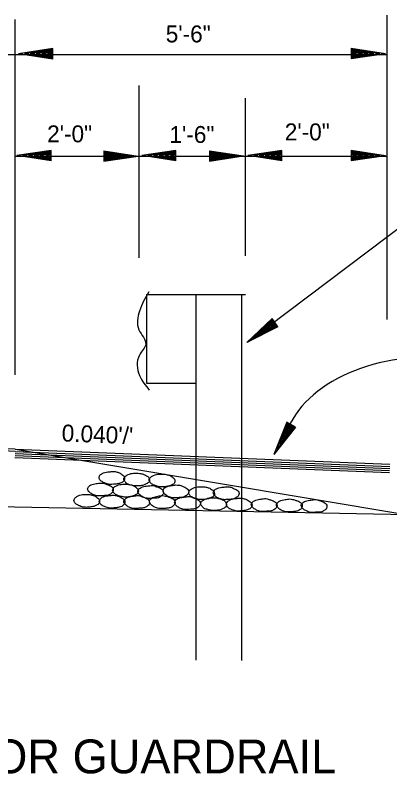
# Model space of a CAD drawing. Extents: x 1955771 to 1955918, y 566326 to 566544.
# Drawn here: x 1955790.88 to 1955804.18, y 566509.34 to 566536.24 of the extents above; entities that cross this region are included whole.
import ezdxf

# ---------------------------------------------------------------- set-up
doc = ezdxf.new("R2010")
doc.units = 0
doc.layers.add('Default', color=7, linetype='Continuous')

msp = doc.modelspace()

# ---------------------------------------------------------------- linework, layer by layer
at = {"layer": 'Default'}
for p, q in [((1955790.882, 566523.482), (1955790.882, 566536.079)), ((1955804.086, 566525.446), (1955804.086, 566536.235)), ((1955792.218, 566535.048), (1955791.001, 566534.866)), ((1955792.218, 566535.017), (1955791.205, 566534.866)), ((1955792.218, 566534.985), (1955791.414, 566534.866)), ((1955792.218, 566534.681), (1955792.218, 566535.048)), ((1955802.808, 566535.061), (1955804.026, 566534.876)), ((1955802.808, 566535.061), (1955802.808, 566534.694)), ((1955802.808, 566535.029), (1955803.821, 566534.876)), ((1955802.808, 566534.997), (1955803.612, 566534.876)), ((1955771.442, 566534.844), (1955804.086, 566534.844)), ((1955792.218, 566534.681), (1955791.001, 566534.866)), ((1955792.218, 566534.713), (1955791.205, 566534.866)), ((1955792.218, 566534.745), (1955791.414, 566534.866)), ((1955792.218, 566534.956), (1955791.618, 566534.866)), ((1955792.218, 566534.774), (1955791.618, 566534.866)), ((1955792.218, 566534.924), (1955791.822, 566534.866)), ((1955792.218, 566534.805), (1955791.822, 566534.866)), ((1955792.218, 566534.893), (1955792.026, 566534.866)), ((1955792.218, 566534.837), (1955792.026, 566534.866)), ((1955802.808, 566534.968), (1955803.408, 566534.876)), ((1955802.808, 566534.937), (1955803.204, 566534.876)), ((1955802.808, 566534.905), (1955803, 566534.876)), ((1955802.808, 566534.694), (1955804.026, 566534.876)), ((1955802.808, 566534.818), (1955803.204, 566534.876)), ((1955802.808, 566534.757), (1955803.612, 566534.876)), ((1955802.808, 566534.725), (1955803.821, 566534.876)), ((1955802.808, 566534.786), (1955803.408, 566534.876)), ((1955802.808, 566534.849), (1955803, 566534.876)), ((1955795.282, 566527.628), (1955795.282, 566533.739)), ((1955799.056, 566527.707), (1955799.056, 566533.294)), ((1955790.882, 566531.233), (1955804.086, 566531.233)), ((1955792.153, 566531.437), (1955790.935, 566531.255)), ((1955792.153, 566531.07), (1955790.935, 566531.255)), ((1955792.153, 566531.406), (1955791.139, 566531.255)), ((1955792.153, 566531.102), (1955791.139, 566531.255)), ((1955792.153, 566531.374), (1955791.348, 566531.255)), ((1955792.153, 566531.134), (1955791.348, 566531.255)), ((1955792.153, 566531.345), (1955791.552, 566531.255)), ((1955792.153, 566531.163), (1955791.552, 566531.255)), ((1955792.153, 566531.313), (1955791.757, 566531.255)), ((1955792.153, 566531.194), (1955791.757, 566531.255)), ((1955792.153, 566531.282), (1955791.961, 566531.255)), ((1955792.153, 566531.226), (1955791.961, 566531.255)), ((1955792.153, 566531.07), (1955792.153, 566531.437)), ((1955794.031, 566531.425), (1955795.248, 566531.241)), ((1955794.031, 566531.425), (1955794.031, 566531.058)), ((1955794.031, 566531.394), (1955795.044, 566531.241)), ((1955794.031, 566531.362), (1955794.835, 566531.241)), ((1955794.031, 566531.333), (1955794.631, 566531.241)), ((1955794.031, 566531.301), (1955794.427, 566531.241)), ((1955794.031, 566531.27), (1955794.223, 566531.241)), ((1955794.031, 566531.058), (1955795.248, 566531.241)), ((1955794.031, 566531.182), (1955794.427, 566531.241)), ((1955794.031, 566531.121), (1955794.835, 566531.241)), ((1955794.031, 566531.09), (1955795.044, 566531.241)), ((1955794.031, 566531.151), (1955794.631, 566531.241)), ((1955794.031, 566531.214), (1955794.223, 566531.241)), ((1955796.587, 566531.437), (1955795.37, 566531.255)), ((1955796.587, 566531.07), (1955795.37, 566531.255)), ((1955796.587, 566531.406), (1955795.574, 566531.255)), ((1955796.587, 566531.102), (1955795.574, 566531.255)), ((1955796.587, 566531.374), (1955795.783, 566531.255)), ((1955796.587, 566531.134), (1955795.783, 566531.255)), ((1955796.587, 566531.345), (1955795.987, 566531.255)), ((1955796.587, 566531.163), (1955795.987, 566531.255)), ((1955796.587, 566531.313), (1955796.191, 566531.255)), ((1955796.587, 566531.194), (1955796.191, 566531.255)), ((1955796.587, 566531.282), (1955796.395, 566531.255)), ((1955796.587, 566531.226), (1955796.395, 566531.255)), ((1955796.587, 566531.07), (1955796.587, 566531.437)), ((1955797.771, 566531.428), (1955798.988, 566531.243)), ((1955797.771, 566531.428), (1955797.771, 566531.061)), ((1955797.771, 566531.396), (1955798.784, 566531.243)), ((1955797.771, 566531.364), (1955798.575, 566531.243)), ((1955797.771, 566531.335), (1955798.371, 566531.243)), ((1955797.771, 566531.304), (1955798.167, 566531.243)), ((1955797.771, 566531.272), (1955797.963, 566531.243)), ((1955797.771, 566531.061), (1955798.988, 566531.243)), ((1955797.771, 566531.185), (1955798.167, 566531.243)), ((1955797.771, 566531.124), (1955798.575, 566531.243)), ((1955797.771, 566531.092), (1955798.784, 566531.243)), ((1955797.771, 566531.153), (1955798.371, 566531.243)), ((1955797.771, 566531.216), (1955797.963, 566531.243)), ((1955800.349, 566531.44), (1955799.132, 566531.258)), ((1955800.349, 566531.073), (1955799.132, 566531.258)), ((1955800.349, 566531.408), (1955799.336, 566531.258)), ((1955800.349, 566531.104), (1955799.336, 566531.258)), ((1955800.349, 566531.377), (1955799.545, 566531.258)), ((1955800.349, 566531.136), (1955799.545, 566531.258)), ((1955800.349, 566531.347), (1955799.749, 566531.258)), ((1955800.349, 566531.165), (1955799.749, 566531.258)), ((1955800.349, 566531.316), (1955799.953, 566531.258)), ((1955800.349, 566531.197), (1955799.953, 566531.258)), ((1955800.349, 566531.284), (1955800.157, 566531.258)), ((1955800.349, 566531.228), (1955800.157, 566531.258)), ((1955800.349, 566531.073), (1955800.349, 566531.44)), ((1955802.808, 566531.447), (1955804.026, 566531.262)), ((1955802.808, 566531.447), (1955802.808, 566531.08)), ((1955802.808, 566531.416), (1955803.821, 566531.262)), ((1955802.808, 566531.384), (1955803.612, 566531.262)), ((1955802.808, 566531.355), (1955803.408, 566531.262)), ((1955802.808, 566531.323), (1955803.204, 566531.262)), ((1955802.808, 566531.292), (1955803, 566531.262)), ((1955802.808, 566531.08), (1955804.026, 566531.262)), ((1955802.808, 566531.204), (1955803.204, 566531.262)), ((1955802.808, 566531.143), (1955803.612, 566531.262)), ((1955802.808, 566531.112), (1955803.821, 566531.262)), ((1955802.808, 566531.173), (1955803.408, 566531.262)), ((1955802.808, 566531.236), (1955803, 566531.262)), ((1955799.136, 566524.648), (1955805.982, 566529.821)), ((1955795.535, 566526.327), (1955795.535, 566523.183)), ((1955795.535, 566526.327), (1955799.056, 566526.327)), ((1955797.297, 566526.327), (1955797.297, 566513.37)), ((1955798.915, 566526.313), (1955798.915, 566513.358)), ((1955800, 566525.479), (1955799.105, 566524.634)), ((1955800.019, 566525.456), (1955799.271, 566524.748)), ((1955800.039, 566525.426), (1955799.448, 566524.874)), ((1955800.051, 566525.401), (1955799.613, 566524.988)), ((1955800.07, 566525.38), (1955799.778, 566525.105)), ((1955800.087, 566525.353), (1955799.946, 566525.222)), ((1955800.121, 566525.312), (1955799.946, 566525.222)), ((1955800.206, 566525.183), (1955800, 566525.479)), ((1955800.206, 566525.183), (1955799.105, 566524.634)), ((1955800.192, 566525.205), (1955799.271, 566524.748)), ((1955800.17, 566525.232), (1955799.448, 566524.874)), ((1955800.153, 566525.258), (1955799.613, 566524.988)), ((1955800.134, 566525.285), (1955799.778, 566525.105)), ((1955795.535, 566523.183), (1955797.297, 566523.183)), ((1955800.517, 566521.807), (1955800.065, 566520.66)), ((1955800.833, 566521.623), (1955800.517, 566521.807)), ((1955800.833, 566521.623), (1955800.065, 566520.66)), ((1955800.541, 566521.788), (1955800.167, 566520.838)), ((1955800.808, 566521.64), (1955800.167, 566520.838)), ((1955800.57, 566521.773), (1955800.271, 566521.02)), ((1955800.777, 566521.652), (1955800.271, 566521.02)), ((1955800.594, 566521.759), (1955800.371, 566521.192)), ((1955800.752, 566521.669), (1955800.371, 566521.192)), ((1955800.624, 566521.744), (1955800.475, 566521.372)), ((1955800.726, 566521.683), (1955800.475, 566521.372)), ((1955800.653, 566521.727), (1955800.58, 566521.547)), ((1955800.699, 566521.7), (1955800.58, 566521.547)), ((1955790.882, 566520.843), (1955776.302, 566521.426)), ((1955790.882, 566520.77), (1955776.302, 566521.353)), ((1955790.878, 566520.77), (1955804.177, 566520.238)), ((1955790.882, 566520.843), (1955804.181, 566520.31)), ((1955790.882, 566520.843), (1955814.346, 566516.93)), ((1955790.87, 566520.551), (1955804.169, 566520.019)), ((1955790.872, 566520.624), (1955804.171, 566520.092)), ((1955790.875, 566520.697), (1955804.175, 566520.165)), ((1955771.003, 566519.197), (1955809.855, 566518.425))]:
    msp.add_line(p, q, dxfattribs=at)
msp.add_ellipse((1955806.375, 566520.125), major_axis=(-6.005, 0.733), ratio=0.655798, start_param=4.712389, end_param=6.093533, dxfattribs=at)
for points in [[(1955795.62, 566526.429), (1955795.29, 566525.746), (1955795.273, 566525.08), (1955795.511, 566524.568), (1955795.29, 566524.179), (1955795.29, 566523.462), (1955795.64, 566522.945)], [(1955794.325, 566520.051), (1955794.165, 566520.041), (1955793.97, 566519.983), (1955793.868, 566519.891), (1955793.854, 566519.837), (1955793.902, 566519.74), (1955793.961, 566519.696), (1955794.072, 566519.643), (1955794.228, 566519.599), (1955794.31, 566519.599), (1955794.427, 566519.609), (1955794.558, 566519.624), (1955794.66, 566519.662), (1955794.748, 566519.745), (1955794.762, 566519.808), (1955794.733, 566519.896), (1955794.67, 566519.954), (1955794.602, 566519.993), (1955794.495, 566520.037), (1955794.427, 566520.051), (1955794.325, 566520.051)], [(1955795.196, 566519.999), (1955795.035, 566519.99), (1955794.846, 566519.922), (1955794.749, 566519.844), (1955794.734, 566519.79), (1955794.788, 566519.688), (1955794.831, 566519.635), (1955794.948, 566519.586), (1955795.094, 566519.552), (1955795.176, 566519.543), (1955795.298, 566519.547), (1955795.434, 566519.572), (1955795.531, 566519.615), (1955795.633, 566519.693), (1955795.648, 566519.756), (1955795.619, 566519.844), (1955795.546, 566519.907), (1955795.473, 566519.941), (1955795.366, 566519.975), (1955795.298, 566519.99), (1955795.196, 566519.999)], [(1955796.102, 566519.963), (1955795.942, 566519.958), (1955795.747, 566519.89), (1955795.65, 566519.803), (1955795.636, 566519.744), (1955795.689, 566519.647), (1955795.743, 566519.603), (1955795.849, 566519.555), (1955796.005, 566519.511), (1955796.088, 566519.506), (1955796.204, 566519.516), (1955796.335, 566519.54), (1955796.438, 566519.579), (1955796.535, 566519.657), (1955796.549, 566519.715), (1955796.52, 566519.803), (1955796.447, 566519.861), (1955796.379, 566519.909), (1955796.272, 566519.943), (1955796.204, 566519.958), (1955796.102, 566519.963)], [(1955793.922, 566519.645), (1955793.752, 566519.626), (1955793.563, 566519.577), (1955793.466, 566519.485), (1955793.451, 566519.432), (1955793.5, 566519.329), (1955793.558, 566519.286), (1955793.665, 566519.227), (1955793.82, 566519.189), (1955793.898, 566519.189), (1955794.02, 566519.198), (1955794.156, 566519.208), (1955794.258, 566519.257), (1955794.345, 566519.339), (1955794.36, 566519.402), (1955794.331, 566519.49), (1955794.258, 566519.548), (1955794.19, 566519.577), (1955794.083, 566519.621), (1955794.02, 566519.641), (1955793.922, 566519.645)], [(1955794.805, 566519.604), (1955794.644, 566519.599), (1955794.45, 566519.536), (1955794.353, 566519.444), (1955794.338, 566519.39), (1955794.391, 566519.288), (1955794.445, 566519.244), (1955794.552, 566519.196), (1955794.707, 566519.157), (1955794.79, 566519.147), (1955794.907, 566519.157), (1955795.038, 566519.181), (1955795.14, 566519.22), (1955795.237, 566519.298), (1955795.252, 566519.361), (1955795.223, 566519.449), (1955795.15, 566519.507), (1955795.082, 566519.551), (1955794.975, 566519.585), (1955794.907, 566519.599), (1955794.805, 566519.604)], [(1955795.703, 566519.555), (1955795.542, 566519.54), (1955795.348, 566519.487), (1955795.246, 566519.394), (1955795.231, 566519.341), (1955795.285, 566519.244), (1955795.338, 566519.2), (1955795.45, 566519.137), (1955795.601, 566519.103), (1955795.683, 566519.103), (1955795.8, 566519.112), (1955795.941, 566519.117), (1955796.038, 566519.166), (1955796.131, 566519.248), (1955796.145, 566519.312), (1955796.116, 566519.399), (1955796.048, 566519.457), (1955795.975, 566519.491), (1955795.873, 566519.526), (1955795.805, 566519.555), (1955795.703, 566519.555)], [(1955796.587, 566519.577), (1955796.427, 566519.558), (1955796.237, 566519.509), (1955796.14, 566519.417), (1955796.126, 566519.364), (1955796.179, 566519.261), (1955796.233, 566519.218), (1955796.34, 566519.159), (1955796.495, 566519.121), (1955796.573, 566519.121), (1955796.694, 566519.13), (1955796.826, 566519.14), (1955796.932, 566519.189), (1955797.025, 566519.271), (1955797.039, 566519.334), (1955797.01, 566519.422), (1955796.937, 566519.48), (1955796.864, 566519.509), (1955796.762, 566519.558), (1955796.689, 566519.572), (1955796.587, 566519.577)], [(1955797.506, 566519.514), (1955797.346, 566519.509), (1955797.151, 566519.446), (1955797.054, 566519.354), (1955797.039, 566519.3), (1955797.093, 566519.198), (1955797.146, 566519.155), (1955797.253, 566519.106), (1955797.409, 566519.067), (1955797.491, 566519.057), (1955797.608, 566519.067), (1955797.739, 566519.091), (1955797.841, 566519.13), (1955797.938, 566519.208), (1955797.953, 566519.271), (1955797.924, 566519.359), (1955797.851, 566519.417), (1955797.783, 566519.461), (1955797.676, 566519.495), (1955797.608, 566519.509), (1955797.506, 566519.514)], [(1955798.372, 566519.514), (1955798.211, 566519.495), (1955798.022, 566519.446), (1955797.925, 566519.354), (1955797.91, 566519.3), (1955797.964, 566519.198), (1955798.017, 566519.155), (1955798.124, 566519.096), (1955798.279, 566519.057), (1955798.357, 566519.057), (1955798.479, 566519.067), (1955798.61, 566519.077), (1955798.717, 566519.125), (1955798.809, 566519.208), (1955798.824, 566519.271), (1955798.795, 566519.359), (1955798.722, 566519.417), (1955798.649, 566519.446), (1955798.547, 566519.495), (1955798.474, 566519.509), (1955798.372, 566519.514)], [(1955793.427, 566519.241), (1955793.266, 566519.236), (1955793.072, 566519.168), (1955792.98, 566519.081), (1955792.965, 566519.023), (1955793.014, 566518.925), (1955793.072, 566518.882), (1955793.174, 566518.833), (1955793.334, 566518.789), (1955793.412, 566518.784), (1955793.534, 566518.794), (1955793.665, 566518.818), (1955793.767, 566518.857), (1955793.859, 566518.935), (1955793.874, 566518.993), (1955793.845, 566519.081), (1955793.772, 566519.139), (1955793.704, 566519.188), (1955793.597, 566519.222), (1955793.529, 566519.236), (1955793.427, 566519.241)], [(1955794.326, 566519.213), (1955794.165, 566519.198), (1955793.971, 566519.14), (1955793.879, 566519.052), (1955793.864, 566518.994), (1955793.913, 566518.897), (1955793.961, 566518.853), (1955794.073, 566518.805), (1955794.224, 566518.756), (1955794.306, 566518.756), (1955794.428, 566518.766), (1955794.564, 566518.785), (1955794.661, 566518.819), (1955794.758, 566518.907), (1955794.773, 566518.965), (1955794.744, 566519.052), (1955794.671, 566519.111), (1955794.598, 566519.155), (1955794.496, 566519.193), (1955794.428, 566519.208), (1955794.326, 566519.213)], [(1955795.2, 566519.2), (1955795.039, 566519.18), (1955794.845, 566519.127), (1955794.748, 566519.04), (1955794.733, 566518.981), (1955794.787, 566518.884), (1955794.84, 566518.84), (1955794.947, 566518.782), (1955795.098, 566518.743), (1955795.18, 566518.743), (1955795.302, 566518.753), (1955795.433, 566518.762), (1955795.535, 566518.806), (1955795.632, 566518.894), (1955795.647, 566518.952), (1955795.618, 566519.04), (1955795.545, 566519.098), (1955795.472, 566519.132), (1955795.365, 566519.171), (1955795.302, 566519.195), (1955795.2, 566519.2)], [(1955796.114, 566519.201), (1955795.949, 566519.181), (1955795.755, 566519.128), (1955795.657, 566519.04), (1955795.643, 566518.982), (1955795.696, 566518.885), (1955795.75, 566518.841), (1955795.862, 566518.778), (1955796.012, 566518.744), (1955796.09, 566518.744), (1955796.212, 566518.749), (1955796.348, 566518.763), (1955796.45, 566518.807), (1955796.542, 566518.895), (1955796.557, 566518.953), (1955796.527, 566519.04), (1955796.455, 566519.099), (1955796.382, 566519.133), (1955796.28, 566519.167), (1955796.216, 566519.186), (1955796.114, 566519.201)], [(1955797.01, 566519.164), (1955796.84, 566519.145), (1955796.655, 566519.096), (1955796.553, 566519.004), (1955796.539, 566518.95), (1955796.592, 566518.848), (1955796.646, 566518.805), (1955796.757, 566518.746), (1955796.908, 566518.707), (1955796.986, 566518.707), (1955797.107, 566518.717), (1955797.248, 566518.727), (1955797.346, 566518.775), (1955797.438, 566518.858), (1955797.452, 566518.921), (1955797.423, 566519.009), (1955797.35, 566519.067), (1955797.282, 566519.096), (1955797.175, 566519.135), (1955797.112, 566519.159), (1955797.01, 566519.164)], [(1955797.926, 566519.127), (1955797.766, 566519.117), (1955797.576, 566519.049), (1955797.479, 566518.971), (1955797.465, 566518.918), (1955797.518, 566518.816), (1955797.562, 566518.762), (1955797.678, 566518.714), (1955797.824, 566518.68), (1955797.907, 566518.67), (1955798.028, 566518.675), (1955798.164, 566518.699), (1955798.262, 566518.743), (1955798.364, 566518.821), (1955798.378, 566518.884), (1955798.349, 566518.971), (1955798.276, 566519.035), (1955798.203, 566519.069), (1955798.096, 566519.103), (1955798.028, 566519.117), (1955797.926, 566519.127)], [(1955798.84, 566519.108), (1955798.68, 566519.094), (1955798.485, 566519.035), (1955798.393, 566518.948), (1955798.378, 566518.89), (1955798.427, 566518.792), (1955798.475, 566518.749), (1955798.587, 566518.7), (1955798.738, 566518.652), (1955798.821, 566518.652), (1955798.942, 566518.661), (1955799.078, 566518.681), (1955799.175, 566518.715), (1955799.273, 566518.802), (1955799.287, 566518.861), (1955799.258, 566518.948), (1955799.185, 566519.006), (1955799.112, 566519.05), (1955799.01, 566519.089), (1955798.942, 566519.104), (1955798.84, 566519.108)], [(1955799.727, 566519.094), (1955799.567, 566519.074), (1955799.372, 566519.021), (1955799.275, 566518.933), (1955799.26, 566518.875), (1955799.314, 566518.778), (1955799.367, 566518.734), (1955799.474, 566518.676), (1955799.625, 566518.637), (1955799.707, 566518.637), (1955799.829, 566518.647), (1955799.96, 566518.656), (1955800.062, 566518.7), (1955800.159, 566518.788), (1955800.174, 566518.846), (1955800.145, 566518.933), (1955800.072, 566518.992), (1955799.999, 566519.026), (1955799.892, 566519.065), (1955799.829, 566519.089), (1955799.727, 566519.094)], [(1955800.627, 566519.082), (1955800.462, 566519.062), (1955800.267, 566519.009), (1955800.17, 566518.921), (1955800.155, 566518.863), (1955800.209, 566518.766), (1955800.262, 566518.722), (1955800.374, 566518.659), (1955800.525, 566518.625), (1955800.603, 566518.625), (1955800.724, 566518.63), (1955800.86, 566518.644), (1955800.962, 566518.688), (1955801.055, 566518.775), (1955801.069, 566518.834), (1955801.04, 566518.921), (1955800.967, 566518.98), (1955800.894, 566519.014), (1955800.792, 566519.048), (1955800.729, 566519.067), (1955800.627, 566519.082)], [(1955801.504, 566519.057), (1955801.334, 566519.037), (1955801.144, 566518.988), (1955801.047, 566518.896), (1955801.033, 566518.843), (1955801.086, 566518.745), (1955801.14, 566518.702), (1955801.246, 566518.643), (1955801.402, 566518.6), (1955801.48, 566518.6), (1955801.601, 566518.614), (1955801.737, 566518.619), (1955801.839, 566518.668), (1955801.932, 566518.75), (1955801.946, 566518.814), (1955801.917, 566518.901), (1955801.844, 566518.959), (1955801.771, 566518.993), (1955801.669, 566519.032), (1955801.601, 566519.052), (1955801.504, 566519.057)]]:
    msp.add_spline(points, degree=3, dxfattribs=at)

# ---------------------------------------------------------------- texts
for s, height, p in [('5\'-6"', 0.6, (1955796.223, 566535.27)), ('2\'-0"', 0.6, (1955792.012, 566531.727)), ('1\'-6"', 0.6, (1955796.354, 566531.705)), ('2\'-0"', 0.6, (1955800.449, 566531.797)), ('WIDENING FOR GUARDRAIL', 1.2, (1955780.435, 566509.353))]:
    msp.add_text(s, height=height, dxfattribs=at).set_placement(p)
msp.add_text("0.040'/'", height=0.6, rotation=357.7094, dxfattribs=at).set_placement((1955792.519, 566521.125))

doc.saveas('drawing.dxf')
